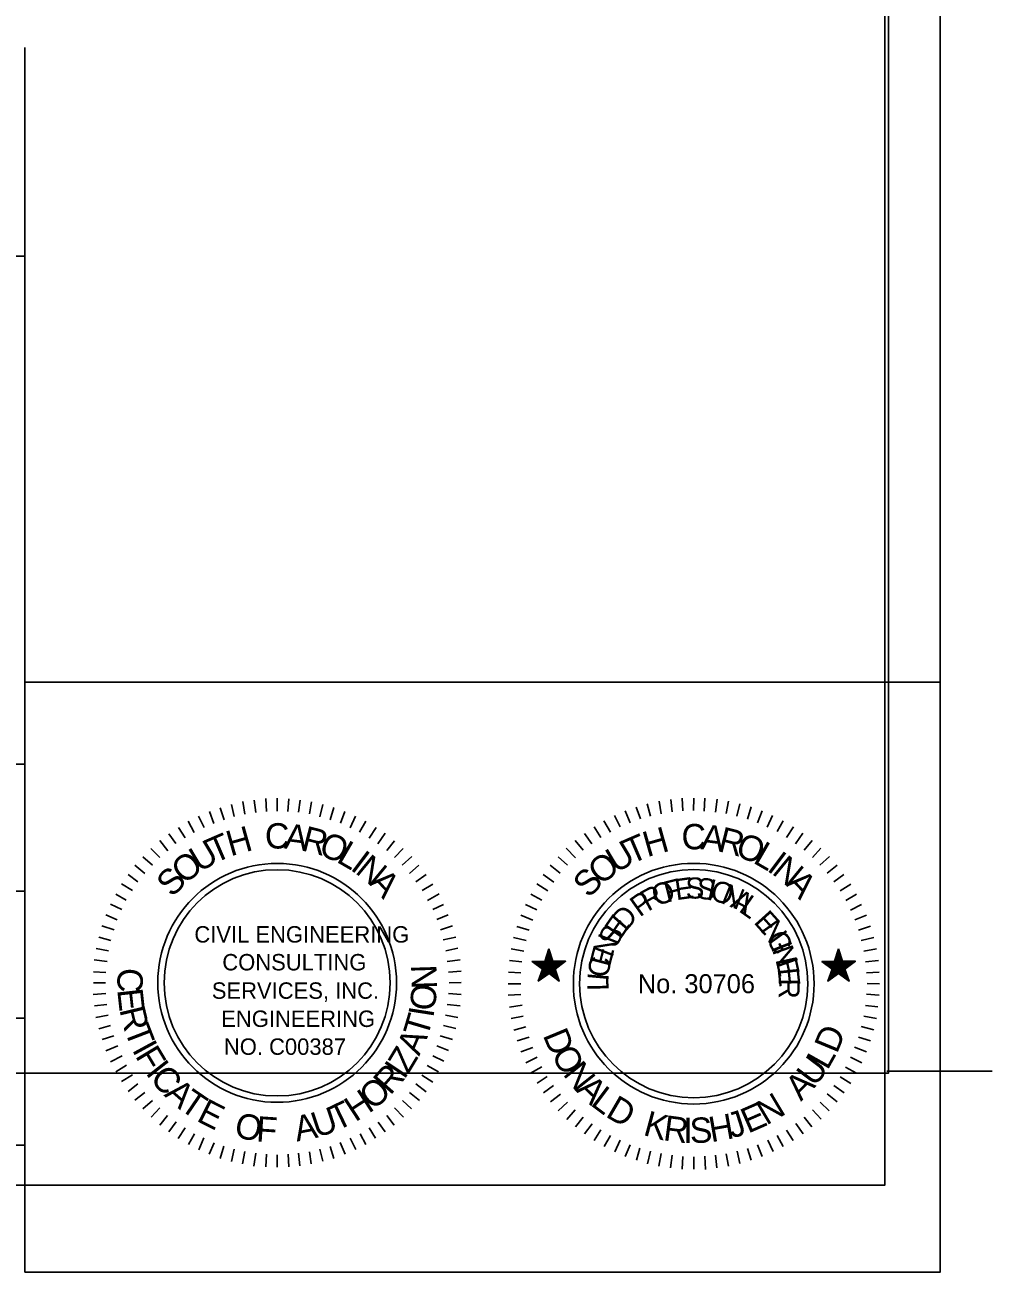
# Model space of a CAD drawing. Extents: x 260980 to 262786, y 322332 to 323393.
# Drawn here: x 262565.2 to 262786, y 322331.9 to 322616.8 of the extents above; entities that cross this region are included whole.
import ezdxf

# ---------------------------------------------------------------- set-up
doc = ezdxf.new("R2010")
doc.units = 0
for name, color, linetype in [('Level 1', 7, 'Continuous'), ('Level 2', 7, 'Continuous'), ('Level 23', 7, 'Continuous'), ('Level 3', 7, 'Continuous'), ('Level 5', 7, 'Continuous'), ('RD_SHT_SEAL_KA', 7, 'Continuous'), ('RD_SHT_TX', 7, 'Continuous')]:
    doc.layers.add(name, color=color, linetype=linetype)

msp = doc.modelspace()

# ---------------------------------------------------------------- linework, layer by layer
at = {"layer": 'Level 1'}
msp.add_lwpolyline([(262565.22, 322466.63), (262774.17, 322466.63), (262774.17, 322331.93), (262565.22, 322331.93)], close=True, dxfattribs=at)
at = {"layer": 'Level 2'}
msp.add_line((262761.95, 322377.79), (262785.98, 322377.79), dxfattribs=at)
at = {"layer": 'Level 23'}
msp.add_lwpolyline([(261111.06, 323336.45), (262761.54, 323336.45), (262761.54, 322351.79), (261111.06, 322351.79)], close=True, dxfattribs=at)
msp.add_lwpolyline([(261111.06, 323336.45), (262761.54, 323336.45), (262761.54, 322351.79), (261111.06, 322351.79)], close=True, dxfattribs=at)
at = {"layer": 'Level 3'}
msp.add_line((262774.17, 322332.83), (262774.17, 323381.93), dxfattribs=at)
at = {"layer": 'Level 5'}
msp.add_lwpolyline([(261111.06, 323310.45), (262762.33, 323310.45), (262762.33, 322377.34), (261111.06, 322377.34)], close=True, dxfattribs=at)
at = {"layer": 'RD_SHT_SEAL_KA'}
for p, q in [((262612.34, 322438.74), (262612.95, 322435.95)), ((262614.94, 322439.36), (262615.42, 322436.48)), ((262617.58, 322439.69), (262617.93, 322436.91)), ((262620.18, 322440.06), (262620.33, 322437.1)), ((262622.82, 322440.13), (262622.81, 322437.22)), ((262625.44, 322440.01), (262625.24, 322437.11)), ((262628.01, 322439.73), (262627.69, 322436.94)), ((262630.62, 322439.35), (262630.15, 322436.61)), ((262633.24, 322438.71), (262632.51, 322435.9)), ((262707.28, 322438.89), (262708.03, 322436.08)), ((262709.98, 322439.48), (262710.46, 322436.56)), ((262712.62, 322439.86), (262712.94, 322437.05)), ((262715.22, 322440.13), (262715.38, 322437.26)), ((262717.92, 322440.18), (262717.86, 322437.37)), ((262720.45, 322440.13), (262720.29, 322437.16)), ((262723.21, 322439.91), (262722.83, 322436.99)), ((262725.85, 322439.48), (262725.31, 322436.67)), ((262728.44, 322438.89), (262727.69, 322436.08)), ((262604.86, 322436.02), (262606.11, 322433.45)), ((262607.32, 322437.14), (262608.37, 322434.41)), ((262609.75, 322437.97), (262610.66, 322435.21)), ((262635.75, 322438.02), (262634.9, 322435.23)), ((262638.21, 322437.1), (262637.27, 322434.45)), ((262640.69, 322436.03), (262639.49, 322433.38)), ((262699.82, 322436.19), (262701.07, 322433.59)), ((262702.25, 322437.26), (262703.34, 322434.51)), ((262704.74, 322438.13), (262705.71, 322435.43)), ((262730.98, 322438.18), (262730.12, 322435.37)), ((262733.52, 322437.26), (262732.44, 322434.56)), ((262735.89, 322436.19), (262734.65, 322433.54)), ((262600.3, 322433.47), (262601.78, 322431.12)), ((262602.47, 322434.9), (262603.86, 322432.35)), ((262643.03, 322434.87), (262641.59, 322432.42)), ((262645.37, 322433.45), (262643.77, 322431.05)), ((262695.18, 322433.59), (262696.69, 322431.21)), ((262697.39, 322435), (262698.85, 322432.41)), ((262738.27, 322435), (262736.92, 322432.51)), ((262740.65, 322433.59), (262739.08, 322431.16)), ((262596.01, 322430.51), (262597.8, 322428.13)), ((262598.06, 322432.04), (262599.68, 322429.78)), ((262647.47, 322432.15), (262645.76, 322429.7)), ((262649.55, 322430.4), (262647.82, 322428.17)), ((262690.81, 322430.51), (262692.64, 322428.25)), ((262692.91, 322432.08), (262694.64, 322429.76)), ((262742.81, 322432.14), (262741.14, 322429.71)), ((262744.92, 322430.51), (262743.08, 322428.3)), ((262593.93, 322428.69), (262596.02, 322426.6)), ((262651.56, 322428.64), (262649.58, 322426.6)), ((262688.75, 322428.73), (262690.86, 322426.57)), ((262746.91, 322428.73), (262745.02, 322426.63)), ((262590.28, 322424.84), (262592.6, 322422.97)), ((262592.16, 322426.75), (262594.3, 322424.83)), ((262653.53, 322426.84), (262651.32, 322424.85)), ((262655.16, 322424.84), (262652.97, 322422.97)), ((262685.14, 322424.84), (262687.4, 322423.01)), ((262686.97, 322426.74), (262689.08, 322424.84)), ((262748.86, 322426.84), (262746.69, 322424.84)), ((262750.59, 322424.84), (262748.37, 322423.01)), ((262588.76, 322422.72), (262591.02, 322421.02)), ((262656.81, 322422.7), (262654.45, 322421.03)), ((262683.52, 322422.74), (262685.94, 322421.01)), ((262752.15, 322422.74), (262749.88, 322421.06)), ((262587.23, 322420.59), (262589.74, 322419.04)), ((262658.31, 322420.54), (262655.89, 322419.05)), ((262682.06, 322420.58), (262684.54, 322418.96)), ((262753.72, 322420.52), (262751.29, 322419.01)), ((262584.73, 322415.92), (262587.3, 322414.71)), ((262585.97, 322418.2), (262588.33, 322416.89)), ((262659.74, 322418.3), (262657.13, 322416.82)), ((262660.79, 322415.9), (262658.33, 322414.7)), ((262679.47, 322415.88), (262682.06, 322414.64)), ((262680.71, 322418.2), (262683.24, 322416.85)), ((262755.07, 322418.2), (262752.58, 322416.8)), ((262756.2, 322415.88), (262753.66, 322414.59)), ((262583.69, 322413.48), (262586.29, 322412.39)), ((262661.83, 322413.5), (262659.21, 322412.42)), ((262678.44, 322413.4), (262681.14, 322412.31)), ((262757.34, 322413.45), (262754.64, 322412.37)), ((262582.74, 322410.98), (262585.57, 322410.1)), ((262662.81, 322411.01), (262660.06, 322410.11)), ((262677.52, 322410.86), (262680.28, 322409.99)), ((262758.25, 322410.91), (262755.5, 322409.99)), ((262582.06, 322408.39), (262584.83, 322407.62)), ((262663.55, 322408.39), (262660.72, 322407.81)), ((262676.77, 322408.32), (262679.63, 322407.62)), ((262759.01, 322408.37), (262756.14, 322407.67)), ((262581.45, 322405.82), (262584.3, 322405.32)), ((262664.05, 322405.88), (262661.26, 322405.27)), ((262676.23, 322405.73), (262679.09, 322405.24)), ((262759.6, 322405.78), (262756.69, 322405.19)), ((262581.03, 322403.24), (262583.95, 322402.82)), ((262664.6, 322403.27), (262661.59, 322402.89)), ((262675.79, 322403.08), (262678.66, 322402.76)), ((262760.04, 322403.08), (262757.12, 322402.81)), ((262580.84, 322400.53), (262583.69, 322400.37)), ((262664.79, 322400.61), (262661.87, 322400.43)), ((262675.58, 322400.44), (262678.44, 322400.27)), ((262760.19, 322400.44), (262757.34, 322400.27)), ((262580.86, 322398), (262583.62, 322397.98)), ((262664.77, 322398.04), (262662.02, 322397.99)), ((262675.52, 322397.79), (262678.39, 322397.79)), ((262760.3, 322397.79), (262757.44, 322397.84)), ((262580.82, 322395.32), (262583.7, 322395.53)), ((262581.07, 322392.74), (262583.94, 322393.02)), ((262664.54, 322392.72), (262661.6, 322393.02)), ((262664.78, 322395.32), (262661.88, 322395.51)), ((262675.52, 322395.14), (262678.39, 322395.31)), ((262760.19, 322395.2), (262757.34, 322395.36)), ((262581.4, 322390.1), (262584.24, 322390.6)), ((262664.06, 322390.05), (262661.23, 322390.59)), ((262675.79, 322392.44), (262678.71, 322392.88)), ((262676.17, 322389.85), (262678.98, 322390.34)), ((262759.6, 322389.85), (262756.69, 322390.39)), ((262759.93, 322392.5), (262757.07, 322392.77)), ((262582.07, 322387.46), (262584.77, 322388.21)), ((262663.55, 322387.53), (262660.74, 322388.26)), ((262676.82, 322387.21), (262679.57, 322387.91)), ((262759.01, 322387.26), (262756.14, 322388.01)), ((262582.82, 322385.03), (262585.51, 322385.85)), ((262662.79, 322385.01), (262660, 322385.85)), ((262677.58, 322384.72), (262680.28, 322385.59)), ((262758.2, 322384.72), (262755.5, 322385.59)), ((262583.66, 322382.45), (262586.39, 322383.57)), ((262661.87, 322382.55), (262659.21, 322383.56)), ((262678.39, 322382.19), (262681.14, 322383.21)), ((262757.34, 322382.24), (262754.58, 322383.26)), ((262584.72, 322379.97), (262587.42, 322381.32)), ((262585.97, 322377.67), (262588.39, 322379.17)), ((262659.61, 322377.69), (262657.05, 322379.08)), ((262660.83, 322380.11), (262658.3, 322381.28)), ((262679.52, 322379.7), (262682.11, 322381)), ((262680.65, 322377.32), (262683.24, 322378.78)), ((262755.07, 322377.38), (262752.53, 322378.73)), ((262756.25, 322379.7), (262753.66, 322381)), ((262587.29, 322375.45), (262589.75, 322376.99)), ((262658.34, 322375.29), (262655.83, 322376.92)), ((262682.11, 322375.06), (262684.44, 322376.57)), ((262753.72, 322375), (262751.29, 322376.51)), ((262588.81, 322373.15), (262591.01, 322374.95)), ((262656.79, 322373.12), (262654.48, 322374.92)), ((262683.57, 322372.84), (262685.89, 322374.57)), ((262752.2, 322372.84), (262749.88, 322374.51)), ((262590.33, 322371.18), (262592.56, 322372.95)), ((262592.14, 322369.17), (262594.32, 322371.12)), ((262653.45, 322369.17), (262651.38, 322371.11)), ((262655.25, 322371.14), (262652.98, 322372.91)), ((262685.19, 322370.79), (262687.46, 322372.57)), ((262686.97, 322368.74), (262689.08, 322370.74)), ((262748.8, 322368.74), (262746.75, 322370.74)), ((262750.64, 322370.79), (262748.37, 322372.63)), ((262594.01, 322367.32), (262596.02, 322369.4)), ((262596.03, 322365.48), (262597.76, 322367.71)), ((262649.52, 322365.47), (262647.82, 322367.72)), ((262651.6, 322367.3), (262649.54, 322369.42)), ((262688.92, 322366.79), (262690.81, 322368.96)), ((262690.86, 322365.12), (262692.64, 322367.28)), ((262744.86, 322365.06), (262743.08, 322367.28)), ((262746.97, 322366.85), (262744.97, 322369.01)), ((262598.08, 322363.95), (262599.77, 322366.21)), ((262600.21, 322362.43), (262601.77, 322364.86)), ((262645.27, 322362.48), (262643.79, 322364.83)), ((262647.47, 322363.95), (262645.82, 322366.16)), ((262692.97, 322363.5), (262694.69, 322365.77)), ((262695.13, 322361.94), (262696.69, 322364.42)), ((262742.86, 322363.5), (262741.19, 322365.82)), ((262602.54, 322361.08), (262603.91, 322363.53)), ((262604.89, 322359.85), (262606.08, 322362.57)), ((262640.75, 322359.91), (262639.49, 322362.54)), ((262643.06, 322361.09), (262641.71, 322363.53)), ((262697.45, 322360.64), (262698.85, 322363.12)), ((262699.88, 322359.4), (262701.07, 322362.04)), ((262736, 322359.45), (262734.76, 322362.04)), ((262738.27, 322360.64), (262736.92, 322363.12)), ((262740.59, 322361.94), (262739.08, 322364.36)), ((262607.29, 322358.85), (262608.38, 322361.44)), ((262609.79, 322357.9), (262610.63, 322360.68)), ((262612.37, 322357.21), (262612.95, 322360)), ((262614.9, 322356.64), (262615.4, 322359.49)), ((262617.5, 322356.14), (262617.91, 322359.06)), ((262620.2, 322355.96), (262620.36, 322358.88)), ((262625.49, 322355.95), (262625.31, 322358.87)), ((262627.99, 322356.19), (262627.67, 322359.09)), ((262630.58, 322356.62), (262630.16, 322359.4)), ((262633.23, 322357.22), (262632.55, 322360)), ((262635.75, 322357.9), (262634.89, 322360.63)), ((262638.28, 322358.85), (262637.19, 322361.55)), ((262702.2, 322358.31), (262703.39, 322361.01)), ((262704.79, 322357.45), (262705.6, 322360.21)), ((262707.33, 322356.64), (262707.98, 322359.51)), ((262709.92, 322356.1), (262710.46, 322359.02)), ((262725.8, 322356.1), (262725.31, 322358.96)), ((262728.44, 322356.7), (262727.79, 322359.51)), ((262730.98, 322357.45), (262730.12, 322360.15)), ((262733.52, 322358.31), (262732.44, 322361.01)), ((262622.81, 322355.91), (262622.8, 322358.7)), ((262712.57, 322355.72), (262712.94, 322358.59)), ((262715.27, 322355.46), (262715.43, 322358.31)), ((262717.92, 322355.4), (262717.92, 322358.26)), ((262720.56, 322355.35), (262720.4, 322358.37)), ((262723.15, 322355.72), (262722.83, 322358.59))]:
    msp.add_line(p, q, dxfattribs=at)
for points in [[(262684.81, 322405.73), (262683.89, 322402.86), (262680.98, 322402.86), (262683.35, 322401.09), (262682.38, 322398.39), (262684.87, 322400.11), (262687.19, 322398.39), (262686.27, 322401.14), (262688.64, 322402.92), (262685.73, 322402.92)], [(262684.76, 322405.3), (262684, 322402.81), (262681.3, 322402.81), (262683.41, 322401.19), (262682.65, 322398.66), (262684.76, 322400.27), (262686.92, 322398.66), (262686.11, 322401.25), (262688.32, 322402.76), (262685.68, 322402.81)], [(262684.87, 322404.92), (262684, 322402.65), (262681.68, 322402.65), (262683.62, 322401.25), (262682.92, 322398.98), (262684.81, 322400.38), (262686.76, 322398.92), (262685.94, 322401.3), (262687.94, 322402.6), (262685.57, 322402.65)], [(262684.87, 322404.54), (262684.11, 322402.54), (262682.06, 322402.49), (262683.79, 322401.3), (262683.14, 322399.3), (262684.76, 322400.54), (262686.54, 322399.3), (262685.94, 322401.3), (262687.57, 322402.6), (262685.46, 322402.49)], [(262750.96, 322405.73), (262749.99, 322402.92), (262747.13, 322402.86), (262749.5, 322401.14), (262748.53, 322398.33), (262750.96, 322400.11), (262753.34, 322398.33), (262752.37, 322401.14), (262754.79, 322402.92), (262751.83, 322402.92)], [(262750.91, 322405.35), (262750.1, 322402.81), (262747.45, 322402.76), (262749.67, 322401.14), (262748.86, 322398.66), (262750.96, 322400.16), (262753.12, 322398.66), (262752.31, 322401.19), (262754.47, 322402.81), (262751.77, 322402.76)], [(262750.96, 322404.92), (262750.26, 322402.6), (262747.83, 322402.65), (262749.77, 322401.25), (262749.07, 322398.92), (262750.96, 322400.38), (262752.91, 322398.98), (262752.15, 322401.19), (262754.09, 322402.71), (262751.72, 322402.65)], [(262750.91, 322404.54), (262750.32, 322402.49), (262748.21, 322402.49), (262749.99, 322401.3), (262749.18, 322399.36), (262750.96, 322400.54), (262752.64, 322399.36), (262751.99, 322401.3), (262753.72, 322402.54), (262751.61, 322402.54)], [(262684.81, 322404.16), (262684.27, 322402.44), (262682.44, 322402.38), (262683.89, 322401.36), (262683.3, 322399.57), (262684.81, 322400.71), (262686.32, 322399.57), (262685.73, 322401.36), (262687.14, 322402.44), (262685.46, 322402.44)], [(262684.81, 322403.79), (262684.38, 322402.27), (262682.82, 322402.33), (262684.06, 322401.41), (262683.57, 322399.95), (262684.87, 322400.87), (262686.11, 322399.9), (262685.57, 322401.41), (262686.87, 322402.22), (262685.3, 322402.27)], [(262684.81, 322403.35), (262684.44, 322402.22), (262683.19, 322402.06), (262684.22, 322401.46), (262683.84, 322400.27), (262684.76, 322400.98), (262685.89, 322400.22), (262685.52, 322401.46), (262686.43, 322402.16), (262685.19, 322402.16)], [(262684.81, 322402.97), (262684.54, 322402.06), (262683.57, 322402.06), (262684.38, 322401.51), (262684.06, 322400.6), (262684.81, 322401.09), (262685.62, 322400.54), (262685.35, 322401.46), (262686.11, 322402), (262685.08, 322402.11)], [(262684.81, 322402.54), (262684.59, 322401.95), (262683.89, 322401.95), (262684.44, 322401.51), (262684.33, 322400.92), (262684.87, 322401.3), (262685.3, 322400.87), (262685.19, 322401.51), (262685.73, 322401.89), (262685.03, 322401.95)], [(262684.87, 322402.22), (262684.65, 322401.84), (262684.33, 322401.84), (262684.65, 322401.57), (262684.49, 322401.19), (262684.87, 322401.46), (262685.08, 322401.19), (262684.97, 322401.62), (262685.3, 322401.79), (262684.97, 322401.79)], [(262684.87, 322401.79), (262684.81, 322401.62), (262684.59, 322401.68), (262684.76, 322401.68), (262684.7, 322401.51), (262684.81, 322401.51), (262684.87, 322401.51), (262684.87, 322401.62), (262685.03, 322401.73), (262684.87, 322401.73)], [(262750.91, 322404.11), (262750.37, 322402.38), (262748.53, 322402.44), (262749.99, 322401.41), (262749.5, 322399.57), (262750.91, 322400.65), (262752.37, 322399.63), (262751.88, 322401.3), (262753.39, 322402.38), (262751.5, 322402.44)], [(262751.02, 322403.73), (262750.48, 322402.33), (262748.91, 322402.33), (262750.21, 322401.46), (262749.67, 322399.9), (262750.96, 322400.81), (262752.15, 322399.95), (262751.77, 322401.36), (262752.91, 322402.27), (262751.45, 322402.33)], [(262750.96, 322403.35), (262750.53, 322402.22), (262749.29, 322402.16), (262750.37, 322401.41), (262749.94, 322400.27), (262750.96, 322401.03), (262751.94, 322400.22), (262751.56, 322401.46), (262752.64, 322402.16), (262751.34, 322402.22)], [(262750.96, 322402.92), (262750.69, 322402.06), (262749.67, 322402.06), (262750.48, 322401.46), (262750.15, 322400.6), (262750.96, 322401.09), (262751.72, 322400.54), (262751.45, 322401.46), (262752.15, 322402.06), (262751.23, 322402.06)], [(262750.96, 322402.6), (262750.64, 322401.95), (262750.1, 322401.89), (262750.59, 322401.57), (262750.37, 322400.92), (262750.96, 322401.25), (262751.5, 322400.87), (262751.29, 322401.46), (262751.88, 322401.89), (262751.23, 322401.95)], [(262750.91, 322402.22), (262750.85, 322401.84), (262750.42, 322401.84), (262750.8, 322401.57), (262750.59, 322401.19), (262751.02, 322401.41), (262751.29, 322401.19), (262751.12, 322401.51), (262751.5, 322401.84), (262751.12, 322401.79)], [(262751.02, 322401.79), (262750.96, 322401.68), (262750.8, 322401.68), (262750.85, 322401.62), (262750.85, 322401.46), (262750.91, 322401.57), (262751.07, 322401.57), (262751.02, 322401.62), (262751.07, 322401.68), (262750.96, 322401.62)]]:
    msp.add_lwpolyline(points, close=True, dxfattribs=at)
for radius in [27.48, 26.04]:
    msp.add_circle((262717.88, 322397.79), radius, dxfattribs=at)
for major_axis in [(0.01, 27.28), (0.01, 25.84)]:
    msp.add_ellipse((262622.79, 322397.98), major_axis=major_axis, ratio=0.998589, dxfattribs=at)
at = {"layer": 'RD_SHT_TX'}
for p, q in [((262565.22, 322389.93), (262565.22, 322611.63)), ((262565.22, 322563.93), (261944.02, 322563.93)), ((262565.22, 322447.93), (261944.02, 322447.93)), ((262565.22, 322418.93), (261944.02, 322418.93)), ((262565.22, 322389.93), (261944.02, 322389.93)), ((262565.22, 322360.93), (261944.02, 322360.93))]:
    msp.add_line(p, q, dxfattribs=at)

# ---------------------------------------------------------------- texts
at = {"layer": 'RD_SHT_SEAL_KA'}
for s, height, rotation, p in [('H', 5.79, 15.7743, (262612.15, 322426.85)), ('C', 5.79, 0.6858, (262620.03, 322428.62)), ('A', 5.79, 352.8136, (262624.25, 322428.71)), ('R', 5.79, 345.657, (262628.07, 322428.29)), ('H', 5.79, 15.7743, (262707.24, 322426.66)), ('C', 5.79, 0.6858, (262715.12, 322428.44)), ('A', 5.79, 352.8136, (262719.35, 322428.53)), ('R', 5.79, 345.657, (262723.16, 322428.1)), ('U', 5.79, 30.8031, (262605.02, 322423.1)), ('T', 5.79, 23.2887, (262608.46, 322425.21)), ('O', 5.79, 338.1426, (262631.99, 322427.34)), ('L', 5.79, 329.9125, (262636.09, 322425.72)), ('U', 5.79, 30.8031, (262700.12, 322422.92)), ('T', 5.79, 23.2887, (262703.56, 322425.02)), ('O', 5.79, 338.1426, (262727.08, 322427.15)), ('L', 5.79, 329.9125, (262731.19, 322425.53)), ('O', 5.79, 39.0332, (262601.61, 322420.3)), ('I', 5.79, 323.1138, (262639.28, 322423.95)), ('N', 5.79, 320.609, (262640.4, 322423.2)), ('O', 5.79, 39.0332, (262696.71, 322420.12)), ('I', 5.79, 323.1138, (262734.38, 322423.76)), ('N', 5.79, 320.609, (262735.5, 322423.02)), ('S', 5.79, 46.5476, (262598.87, 322417.34)), ('A', 5.79, 313.0946, (262643.55, 322420.68)), ('S', 5.79, 46.5476, (262693.97, 322417.15)), ('F', 4.82, 14.3582, (262711.78, 322416.28)), ('E', 4.82, 7.9051, (262713.89, 322416.84)), ('S', 4.82, 1.452, (262716.06, 322417.17)), ('S', 4.82, 354.6762, (262718.36, 322417.24)), ('I', 4.82, 347.9004, (262720.65, 322417.05)), ('A', 5.79, 313.0946, (262738.65, 322420.5)), ('P', 4.82, 35.3308, (262705.56, 322412.88)), ('R', 4.82, 28.555, (262707.43, 322414.22)), ('O', 4.82, 21.7793, (262709.44, 322415.34)), ('O', 4.82, 345.6418, (262721.41, 322416.92)), ('N', 4.82, 338.2207, (262723.85, 322416.3)), ('A', 4.82, 331.445, (262725.99, 322415.46)), ('L', 4.82, 324.9919, (262727.93, 322414.44)), ('E', 4.82, 55.3892, (262701.13, 322407.75)), ('D', 4.82, 48.9361, (262702.35, 322409.57)), ('E', 4.82, 312.0319, (262731.4, 322411.75)), ('CIVIL ENGINEERING', 3.7513, 359.9897, (262603.89, 322407.18)), ('S', 4.82, 62.165, (262700.07, 322405.71)), ('N', 4.82, 305.5788, (262732.89, 322410.14)), ('N', 4.82, 68.9407, (262699.26, 322403.55)), ('G', 4.82, 298.803, (262734.24, 322408.28)), ('I', 4.82, 291.7046, (262735.41, 322406.17)), ('CONSULTING', 3.751, 359.9897, (262610.27, 322400.82)), ('E', 4.82, 75.3939, (262698.73, 322401.43)), ('N', 4.82, 289.446, (262735.73, 322405.47)), ('N', 5.79, 91.8428, (262659.31, 322396.65)), ('C', 4.82, 82.4923, (262698.42, 322399.04)), ('E', 4.82, 282.6702, (262736.51, 322403.31)), ('C', 5.79, 268.515, (262586.4, 322401.43)), ('L', 4.82, 90.8813, (262698.45, 322396.19)), ('I', 4.82, 84.7509, (262698.39, 322398.27)), ('E', 4.82, 276.2171, (262737.01, 322401.18)), ('E', 5.79, 276.3872, (262586.27, 322396.41)), ('SERVICES, INC.', 3.7513, 359.9897, (262607.87, 322394.34)), ('O', 5.79, 83.6128, (262658.74, 322391.43)), ('R', 4.82, 269.764, (262737.27, 322399)), ('R', 5.79, 283.5438, (262586.75, 322391.88)), ('ENGINEERING', 3.7513, 359.9897, (262610.02, 322387.91)), ('T', 5.79, 73.5935, (262657.05, 322385.28)), ('I', 5.79, 81.108, (262658.42, 322389.87)), ('T', 5.79, 291.0582, (262587.86, 322387.22)), ('D', 5.78, 292.563, (262683.37, 322386.04)), ('D', 5.78, 67.437, (262750.56, 322381.63)), ('I', 5.79, 298.5727, (262589.57, 322382.74)), ('NO. C00387', 3.751, 359.9897, (262610.63, 322381.54)), ('A', 5.79, 66.437, (262655.2, 322381.11)), ('F', 5.79, 301.0775, (262590.27, 322381.3)), ('Z', 5.79, 58.9225, (262652.72, 322377.01)), ('O', 5.78, 300.0892, (262685.21, 322381.62)), ('U', 5.78, 53.1014, (262745.54, 322374.04)), ('L', 5.78, 60.6276, (262748.41, 322377.87)), ('I', 5.79, 308.234, (262592.6, 322377.38)), ('R', 5.79, 48.9033, (262648.61, 322372.13)), ('I', 5.79, 56.4177, (262651.77, 322375.73)), ('N', 5.78, 308.3321, (262687.86, 322377.11)), ('C', 5.79, 310.7388, (262593.53, 322376.08)), ('O', 5.79, 40.6733, (262644.65, 322368.7)), ('A', 5.78, 315.8583, (262690.83, 322373.35)), ('A', 5.78, 45.9336, (262742.36, 322370.78)), ('A', 5.79, 318.6111, (262596.8, 322372.28)), ('T', 5.79, 325.7677, (262600.21, 322369.25)), ('H', 5.79, 33.1588, (262640.63, 322366.09)), ('L', 5.78, 323.0261, (262694.09, 322370.17)), ('E', 5.79, 333.2821, (262604.16, 322366.54)), ('T', 5.79, 25.6444, (262636.31, 322364.03)), ('D', 5.78, 329.8355, (262697.53, 322367.54)), ('E', 5.78, 23.6537, (262730.29, 322363.51)), ('N', 5.78, 30.8215, (262734.47, 322365.33)), ('O', 5.79, 348.0127, (262612.76, 322362.84)), ('F', 5.79, 356.2428, (262617.9, 322361.76)), ('A', 5.79, 10.9734, (262627.27, 322361.71)), ('U', 5.79, 18.13, (262631.75, 322362.55)), ('K', 5.78, 344.9476, (262706.13, 322363.28)), ('R', 5.78, 352.4738, (262710.75, 322362.04)), ('S', 5.78, 2.5087, (262717.09, 322361.34)), ('H', 5.78, 10.0349, (262721.87, 322361.55)), ('J', 5.78, 17.5611, (262726.58, 322362.39)), ('I', 5.78, 360, (262715.49, 322361.41))]:
    msp.add_text(s, height=height, rotation=rotation, dxfattribs=at).set_placement(p)
msp.add_text('No. 30706', height=4.336, dxfattribs=at).set_placement((262705.11, 322395.62))

doc.saveas('drawing.dxf')
